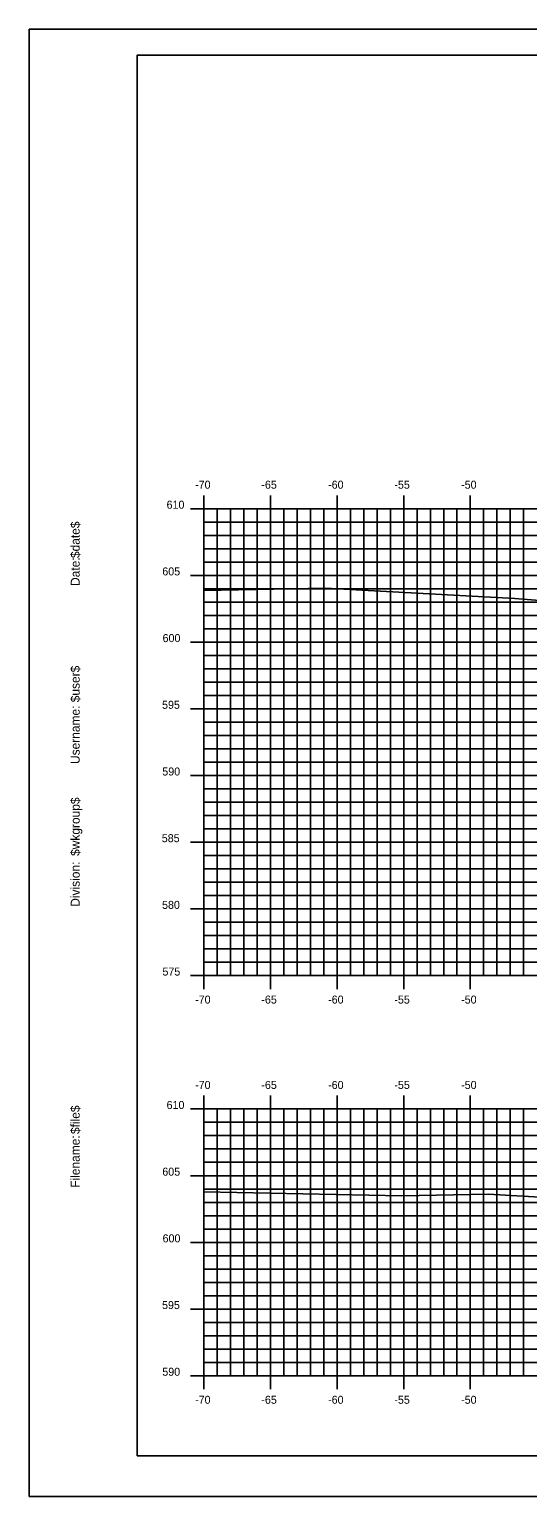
# Model space of a CAD drawing. Extents: x 1076304 to 1076474, y 779716 to 779826.
# Drawn here: x 1076303.7 to 1076341.1, y 779715.6 to 779825.6 of the extents above; entities that cross this region are included whole.
import ezdxf

# ---------------------------------------------------------------- set-up
doc = ezdxf.new("R2010")
doc.units = 0
for name, color, linetype in [('BORDER', 7, 'Continuous'), ('H_V ANNOTATION', 7, 'Continuous'), ('MAJOR', 7, 'Continuous'), ('MINOR', 7, 'Continuous'), ('PLOT BOUNDARY', 7, 'Continuous'), ('S_Roadway_Centerline', 7, 'Continuous')]:
    doc.layers.add(name, color=color, linetype=linetype)

msp = doc.modelspace()

# ---------------------------------------------------------------- linework, layer by layer
at = {"layer": 'BORDER'}
msp.add_lwpolyline([(1076311.79, 779718.71), (1076471.79, 779718.71), (1076471.79, 779823.71), (1076311.79, 779823.71)], close=True, dxfattribs=at)
at = {"layer": 'MAJOR'}
for p, q in [((1076316.79, 779790.71), (1076316.79, 779789.71)), ((1076321.79, 779790.71), (1076321.79, 779789.71)), ((1076326.79, 779790.71), (1076326.79, 779789.71)), ((1076331.79, 779790.71), (1076331.79, 779789.71)), ((1076336.79, 779790.71), (1076336.79, 779789.71)), ((1076315.79, 779789.71), (1076316.79, 779789.71)), ((1076316.79, 779789.71), (1076456.79, 779789.71)), ((1076316.79, 779754.71), (1076316.79, 779789.71)), ((1076316.79, 779754.71), (1076316.79, 779789.71)), ((1076316.79, 779789.71), (1076456.79, 779789.71)), ((1076321.79, 779754.71), (1076321.79, 779789.71)), ((1076326.79, 779754.71), (1076326.79, 779789.71)), ((1076331.79, 779754.71), (1076331.79, 779789.71)), ((1076336.79, 779754.71), (1076336.79, 779789.71)), ((1076315.79, 779784.71), (1076316.79, 779784.71)), ((1076316.79, 779784.71), (1076456.79, 779784.71)), ((1076315.79, 779779.71), (1076316.79, 779779.71)), ((1076316.79, 779779.71), (1076456.79, 779779.71)), ((1076315.79, 779774.71), (1076316.79, 779774.71)), ((1076316.79, 779774.71), (1076456.79, 779774.71)), ((1076315.79, 779769.71), (1076316.79, 779769.71)), ((1076316.79, 779769.71), (1076456.79, 779769.71)), ((1076315.79, 779764.71), (1076316.79, 779764.71)), ((1076316.79, 779764.71), (1076456.79, 779764.71)), ((1076315.79, 779759.71), (1076316.79, 779759.71)), ((1076316.79, 779759.71), (1076456.79, 779759.71)), ((1076315.79, 779754.71), (1076316.79, 779754.71)), ((1076316.79, 779754.71), (1076456.79, 779754.71)), ((1076316.79, 779754.71), (1076456.79, 779754.71)), ((1076316.79, 779753.7), (1076316.79, 779754.71)), ((1076321.79, 779753.7), (1076321.79, 779754.71)), ((1076326.79, 779753.7), (1076326.79, 779754.71)), ((1076331.79, 779753.7), (1076331.79, 779754.71)), ((1076336.79, 779753.7), (1076336.79, 779754.71)), ((1076316.79, 779745.71), (1076316.79, 779744.71)), ((1076321.79, 779745.71), (1076321.79, 779744.71)), ((1076326.79, 779745.71), (1076326.79, 779744.71)), ((1076331.79, 779745.71), (1076331.79, 779744.71)), ((1076336.79, 779745.71), (1076336.79, 779744.71)), ((1076315.79, 779744.71), (1076316.79, 779744.71)), ((1076316.79, 779744.71), (1076386.79, 779744.71)), ((1076316.79, 779724.71), (1076316.79, 779744.71)), ((1076316.79, 779724.71), (1076316.79, 779744.71)), ((1076316.79, 779744.71), (1076386.79, 779744.71)), ((1076321.79, 779724.71), (1076321.79, 779744.71)), ((1076326.79, 779724.71), (1076326.79, 779744.71)), ((1076331.79, 779724.71), (1076331.79, 779744.71)), ((1076336.79, 779724.71), (1076336.79, 779744.71)), ((1076315.79, 779739.71), (1076316.79, 779739.71)), ((1076316.79, 779739.71), (1076386.79, 779739.71)), ((1076315.79, 779734.71), (1076316.79, 779734.71)), ((1076316.79, 779734.71), (1076386.79, 779734.71)), ((1076315.79, 779729.71), (1076316.79, 779729.71)), ((1076316.79, 779729.71), (1076386.79, 779729.71)), ((1076315.79, 779724.71), (1076316.79, 779724.71)), ((1076316.79, 779724.71), (1076386.79, 779724.71)), ((1076316.79, 779724.71), (1076386.79, 779724.71)), ((1076316.79, 779723.7), (1076316.79, 779724.71)), ((1076321.79, 779723.7), (1076321.79, 779724.71)), ((1076326.79, 779723.7), (1076326.79, 779724.71)), ((1076331.79, 779723.7), (1076331.79, 779724.71)), ((1076336.79, 779723.7), (1076336.79, 779724.71))]:
    msp.add_line(p, q, dxfattribs=at)
at = {"layer": 'MINOR'}
for p, q in [((1076317.79, 779754.71), (1076317.79, 779789.71)), ((1076318.79, 779754.71), (1076318.79, 779789.71)), ((1076319.79, 779754.71), (1076319.79, 779789.71)), ((1076320.79, 779754.71), (1076320.79, 779789.71)), ((1076322.79, 779754.71), (1076322.79, 779789.71)), ((1076323.79, 779754.71), (1076323.79, 779789.71)), ((1076324.79, 779754.71), (1076324.79, 779789.71)), ((1076325.79, 779754.71), (1076325.79, 779789.71)), ((1076327.79, 779754.71), (1076327.79, 779789.71)), ((1076328.79, 779754.71), (1076328.79, 779789.71)), ((1076329.79, 779754.71), (1076329.79, 779789.71)), ((1076330.79, 779754.71), (1076330.79, 779789.71)), ((1076332.79, 779754.71), (1076332.79, 779789.71)), ((1076333.79, 779754.71), (1076333.79, 779789.71)), ((1076334.79, 779754.71), (1076334.79, 779789.71)), ((1076335.79, 779754.71), (1076335.79, 779789.71)), ((1076337.79, 779754.71), (1076337.79, 779789.71)), ((1076338.79, 779754.71), (1076338.79, 779789.71)), ((1076339.79, 779754.71), (1076339.79, 779789.71)), ((1076340.79, 779754.71), (1076340.79, 779789.71)), ((1076316.79, 779788.71), (1076456.79, 779788.71)), ((1076316.79, 779788.71), (1076317.8, 779788.71)), ((1076316.79, 779787.71), (1076456.79, 779787.71)), ((1076316.79, 779787.71), (1076317.8, 779787.71)), ((1076316.79, 779786.71), (1076456.79, 779786.71)), ((1076316.79, 779786.71), (1076317.8, 779786.71)), ((1076316.79, 779785.71), (1076456.79, 779785.71)), ((1076316.79, 779785.71), (1076317.8, 779785.71)), ((1076316.79, 779783.71), (1076456.79, 779783.71)), ((1076316.79, 779783.71), (1076317.8, 779783.71)), ((1076316.79, 779782.71), (1076456.79, 779782.71)), ((1076316.79, 779782.71), (1076317.8, 779782.71)), ((1076316.79, 779781.71), (1076456.79, 779781.71)), ((1076316.79, 779781.71), (1076317.8, 779781.71)), ((1076316.79, 779780.71), (1076456.79, 779780.71)), ((1076316.79, 779780.71), (1076317.8, 779780.71)), ((1076316.79, 779778.71), (1076456.79, 779778.71)), ((1076316.79, 779778.71), (1076317.8, 779778.71)), ((1076316.79, 779777.71), (1076456.79, 779777.71)), ((1076316.79, 779777.71), (1076317.8, 779777.71)), ((1076316.79, 779776.71), (1076456.79, 779776.71)), ((1076316.79, 779776.71), (1076317.8, 779776.71)), ((1076316.79, 779775.71), (1076456.79, 779775.71)), ((1076316.79, 779775.71), (1076317.8, 779775.71)), ((1076316.79, 779773.71), (1076456.79, 779773.71)), ((1076316.79, 779773.71), (1076317.8, 779773.71)), ((1076316.79, 779772.71), (1076456.79, 779772.71)), ((1076316.79, 779772.71), (1076317.8, 779772.71)), ((1076316.79, 779771.71), (1076456.79, 779771.71)), ((1076316.79, 779771.71), (1076317.8, 779771.71)), ((1076316.79, 779770.71), (1076456.79, 779770.71)), ((1076316.79, 779770.71), (1076317.8, 779770.71)), ((1076316.79, 779768.71), (1076456.79, 779768.71)), ((1076316.79, 779768.71), (1076317.8, 779768.71)), ((1076316.79, 779767.71), (1076456.79, 779767.71)), ((1076316.79, 779767.71), (1076317.8, 779767.71)), ((1076316.79, 779766.71), (1076456.79, 779766.71)), ((1076316.79, 779766.71), (1076317.8, 779766.71)), ((1076316.79, 779765.71), (1076456.79, 779765.71)), ((1076316.79, 779765.71), (1076317.8, 779765.71)), ((1076316.79, 779763.71), (1076456.79, 779763.71)), ((1076316.79, 779763.71), (1076317.8, 779763.71)), ((1076316.79, 779762.71), (1076456.79, 779762.71)), ((1076316.79, 779762.71), (1076317.8, 779762.71)), ((1076316.79, 779761.71), (1076456.79, 779761.71)), ((1076316.79, 779761.71), (1076317.8, 779761.71)), ((1076316.79, 779760.71), (1076456.79, 779760.71)), ((1076316.79, 779760.71), (1076317.8, 779760.71)), ((1076316.79, 779758.71), (1076456.79, 779758.71)), ((1076316.79, 779758.71), (1076317.8, 779758.71)), ((1076316.79, 779757.71), (1076456.79, 779757.71)), ((1076316.79, 779757.71), (1076317.8, 779757.71)), ((1076316.79, 779756.71), (1076456.79, 779756.71)), ((1076316.79, 779756.71), (1076317.8, 779756.71)), ((1076316.79, 779755.71), (1076456.79, 779755.71)), ((1076316.79, 779755.71), (1076317.8, 779755.71)), ((1076316.79, 779724.71), (1076316.79, 779744.71)), ((1076317.79, 779724.71), (1076317.79, 779744.71)), ((1076318.79, 779724.71), (1076318.79, 779744.71)), ((1076319.79, 779724.71), (1076319.79, 779744.71)), ((1076320.79, 779724.71), (1076320.79, 779744.71)), ((1076322.79, 779724.71), (1076322.79, 779744.71)), ((1076323.79, 779724.71), (1076323.79, 779744.71)), ((1076324.79, 779724.71), (1076324.79, 779744.71)), ((1076325.79, 779724.71), (1076325.79, 779744.71)), ((1076327.79, 779724.71), (1076327.79, 779744.71)), ((1076328.79, 779724.71), (1076328.79, 779744.71)), ((1076329.79, 779724.71), (1076329.79, 779744.71)), ((1076330.79, 779724.71), (1076330.79, 779744.71)), ((1076332.79, 779724.71), (1076332.79, 779744.71)), ((1076333.79, 779724.71), (1076333.79, 779744.71)), ((1076334.79, 779724.71), (1076334.79, 779744.71)), ((1076335.79, 779724.71), (1076335.79, 779744.71)), ((1076337.79, 779724.71), (1076337.79, 779744.71)), ((1076338.79, 779724.71), (1076338.79, 779744.71)), ((1076339.79, 779724.71), (1076339.79, 779744.71)), ((1076340.79, 779724.71), (1076340.79, 779744.71)), ((1076316.79, 779743.71), (1076386.79, 779743.71)), ((1076316.79, 779743.71), (1076317.8, 779743.71)), ((1076316.79, 779742.71), (1076386.79, 779742.71)), ((1076316.79, 779742.71), (1076317.8, 779742.71)), ((1076316.79, 779741.71), (1076386.79, 779741.71)), ((1076316.79, 779741.71), (1076317.8, 779741.71)), ((1076316.79, 779740.71), (1076386.79, 779740.71)), ((1076316.79, 779740.71), (1076317.8, 779740.71)), ((1076316.79, 779738.71), (1076386.79, 779738.71)), ((1076316.79, 779738.71), (1076317.8, 779738.71)), ((1076316.79, 779737.71), (1076386.79, 779737.71)), ((1076316.79, 779737.71), (1076317.8, 779737.71)), ((1076316.79, 779736.71), (1076386.79, 779736.71)), ((1076316.79, 779736.71), (1076317.8, 779736.71)), ((1076316.79, 779735.71), (1076386.79, 779735.71)), ((1076316.79, 779735.71), (1076317.8, 779735.71)), ((1076316.79, 779733.71), (1076386.79, 779733.71)), ((1076316.79, 779733.71), (1076317.8, 779733.71)), ((1076316.79, 779732.71), (1076386.79, 779732.71)), ((1076316.79, 779732.71), (1076317.8, 779732.71)), ((1076316.79, 779731.71), (1076386.79, 779731.71)), ((1076316.79, 779731.71), (1076317.8, 779731.71)), ((1076316.79, 779730.71), (1076386.79, 779730.71)), ((1076316.79, 779730.71), (1076317.8, 779730.71)), ((1076316.79, 779728.71), (1076386.79, 779728.71)), ((1076316.79, 779728.71), (1076317.8, 779728.71)), ((1076316.79, 779727.71), (1076386.79, 779727.71)), ((1076316.79, 779727.71), (1076317.8, 779727.71)), ((1076316.79, 779726.71), (1076386.79, 779726.71)), ((1076316.79, 779726.71), (1076317.8, 779726.71)), ((1076316.79, 779725.71), (1076386.79, 779725.71)), ((1076316.79, 779725.71), (1076317.8, 779725.71))]:
    msp.add_line(p, q, dxfattribs=at)
at = {"layer": 'PLOT BOUNDARY'}
msp.add_lwpolyline([(1076303.7, 779715.65), (1076473.7, 779715.65), (1076473.7, 779825.65), (1076303.7, 779825.65)], close=True, dxfattribs=at)
at = {"layer": 'S_Roadway_Centerline'}
for points in [[(1076316.79, 779783.59), (1076325.92, 779783.75), (1076340.12, 779782.98), (1076355.63, 779781.74), (1076358.2, 779781.66), (1076359.93, 779781.55), (1076362.18, 779781.65), (1076363.83, 779781.68), (1076363.94, 779781.68), (1076363.94, 779781.68), (1076374.23, 779782.04), (1076383.82, 779781.51), (1076386.61, 779781.45), (1076389.09, 779781.27), (1076397.21, 779780.5), (1076401.43, 779780.09), (1076402.49, 779779.99), (1076404.07, 779780.36), (1076405.08, 779780.53), (1076406.79, 779780.86), (1076407.84, 779781.1), (1076411.9, 779779.04), (1076416.12, 779777.15)], [(1076316.79, 779738.51), (1076331.64, 779738.2), (1076338.12, 779738.32), (1076342.89, 779738.06), (1076348.17, 779737.64), (1076349.84, 779737.58), (1076365.34, 779737.47), (1076366.86, 779737.5), (1076369.68, 779737.49), (1076369.83, 779737.48), (1076373.9, 779737.62), (1076380.65, 779737.24), (1076386.58, 779736.93), (1076386.79, 779736.9)]]:
    msp.add_lwpolyline(points, dxfattribs=at)

# ---------------------------------------------------------------- texts
at = {"layer": 'BORDER'}
for s, p in [('$date$', (1076307.48, 779786.01)), ('Date:', (1076307.48, 779783.92)), ('$user$', (1076307.48, 779775.2)), ('Username:', (1076307.48, 779770.57)), ('$wkgroup$', (1076307.48, 779763.68)), ('Division:', (1076307.48, 779759.87)), ('$file$', (1076307.48, 779742.83)), ('Filename:', (1076307.48, 779738.8))]:
    msp.add_text(s, height=0.67, rotation=90, dxfattribs=at).set_placement(p)
at = {"layer": 'H_V ANNOTATION'}
for s, p in [('-70', (1076316.14, 779791.21)), ('-65', (1076321.11, 779791.21)), ('-60', (1076326.12, 779791.21)), ('-55', (1076331.09, 779791.21)), ('-50', (1076336.1, 779791.21)), ('610', (1076314, 779789.71)), ('605', (1076313.68, 779784.71)), ('600', (1076313.7, 779779.71)), ('595', (1076313.66, 779774.71)), ('590', (1076313.68, 779769.71)), ('585', (1076313.64, 779764.71)), ('580', (1076313.66, 779759.71)), ('575', (1076313.69, 779754.71)), ('-70', (1076316.14, 779752.61)), ('-65', (1076321.11, 779752.61)), ('-60', (1076326.12, 779752.61)), ('-55', (1076331.09, 779752.61)), ('-50', (1076336.1, 779752.61)), ('-70', (1076316.14, 779746.21)), ('-65', (1076321.11, 779746.21)), ('-60', (1076326.12, 779746.21)), ('-55', (1076331.09, 779746.21)), ('-50', (1076336.1, 779746.21)), ('610', (1076314, 779744.71)), ('605', (1076313.68, 779739.71)), ('600', (1076313.7, 779734.71)), ('595', (1076313.66, 779729.71)), ('590', (1076313.68, 779724.71)), ('-70', (1076316.14, 779722.61)), ('-65', (1076321.11, 779722.61)), ('-60', (1076326.12, 779722.61)), ('-55', (1076331.09, 779722.61)), ('-50', (1076336.1, 779722.61))]:
    msp.add_text(s, height=0.6, dxfattribs=at).set_placement(p)
at = {"layer": 'MAJOR'}
for p in [(1076316.79, 779754.71), (1076316.79, 779724.71)]:
    msp.add_text('-', height=0.006, dxfattribs=at).set_placement(p)

doc.saveas('drawing.dxf')
